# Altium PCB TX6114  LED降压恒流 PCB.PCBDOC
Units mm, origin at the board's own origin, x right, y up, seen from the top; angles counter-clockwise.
Board outline 33.78 x 21.25 mm, 2 copper layers (TopLayer, BottomLayer); 21 components, 9 nets, 48 pads, 36 vias.
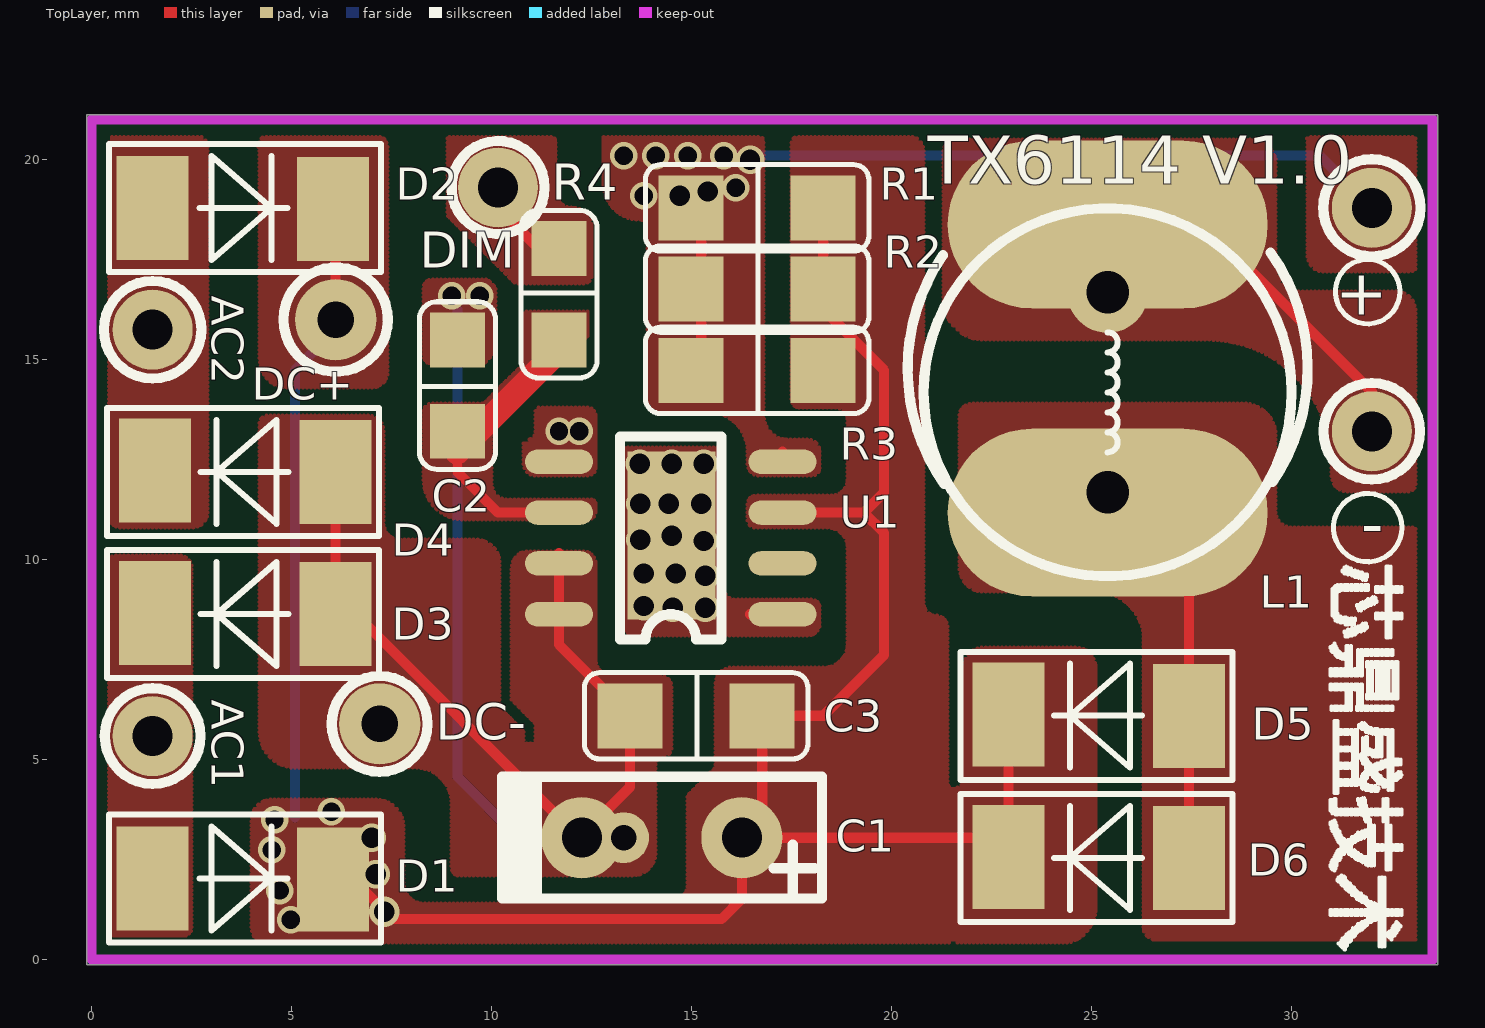
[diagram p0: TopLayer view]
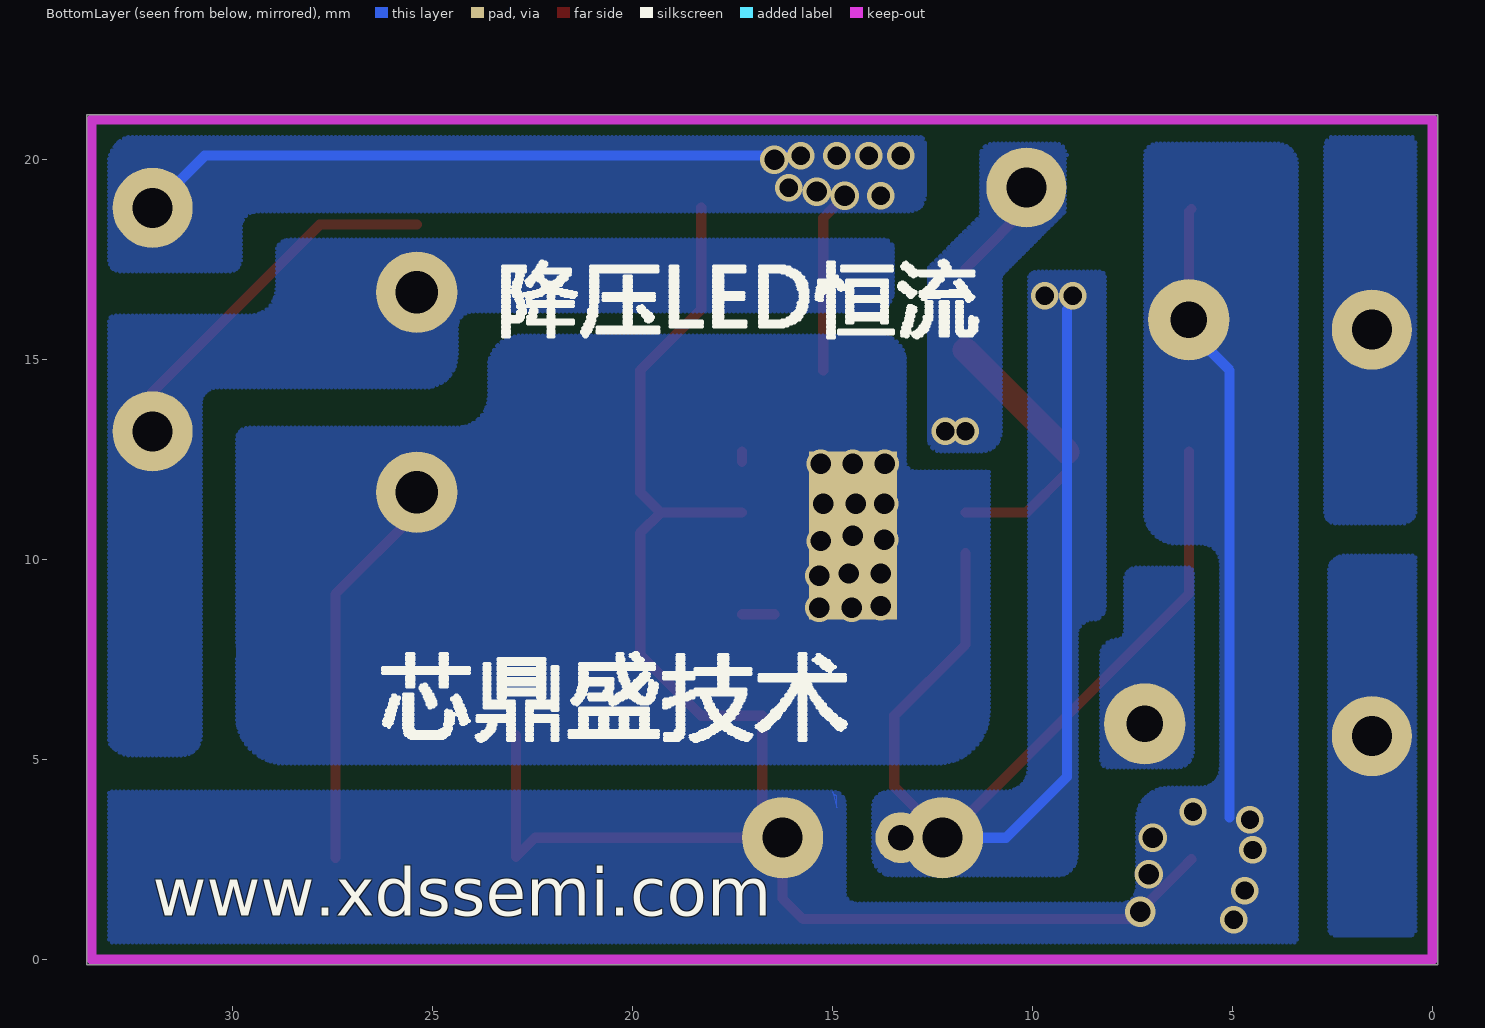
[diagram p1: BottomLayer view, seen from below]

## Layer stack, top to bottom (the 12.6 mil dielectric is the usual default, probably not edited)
TopLayer: signal copper 0.0356
Dielectric: dielectric 0.32, FR-4, Dk 4.8
BottomLayer: signal copper 0.0356

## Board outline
-0.127,-0.127 33.655,-0.127 33.655,21.127 -0.127,21.127

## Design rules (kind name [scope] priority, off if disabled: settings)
Clearance [All] p1: gap=0.254
ComponentClearance [All] p1 off: gap=0.254 collisioncheckmode=3 verticalgap=0.254 showdistances=FALSE
PolygonConnect [All] p1: connectstyle=Direct reliefconductorwidth=0.254 reliefentries=4 polygonreliefangle="90 Angle"
RoutingVias [All] p1: holewidth=0.711 width=1.27 viastyle="Through Hole" minholewidth=0.711 minwidth=1.27 maxholewidth=0.711 maxwidth=1.27
SilkscreenOverComponentPads [All] p1: minsilkscreentomaskgap=0.254
SolderMaskExpansion [All] p1: expansion=0.102
TestPointUsage [All] p1: valid=0 allowmultiple=FALSE
Testpoint [All] p1: side=15 testpointundercomponent=TRUE minsize=1.016 maxsize=2.54 preferedsize=1.524 minholesize=0.508 maxholesize=1.016 preferedholesize=0.813 testpointgrid=0.025 style=1023 order=0123456789
Width [All] p1: maxlimit=0.254 minlimit=0.254 preferedwidth=0.254
22 further rules are at their usual default settings.

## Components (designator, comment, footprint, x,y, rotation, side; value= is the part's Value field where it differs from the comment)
+ "" PAD 32.004,18.796 r0 top
- "" PAD 32.004,13.208 r0 top
AC1 "" PAD 1.524,5.588 r0 top
AC2 "" PAD 1.524,15.748 r0 top
C1 "" C8X 16.256,3.048 r90 top
C2 "" R0805 9.144,13.208 r0 top
C3 "" R1206 16.764,6.096 r270 top
D1 "" SMB 1.524,2.032 r0 top
D2 "" SMB 1.524,18.796 r0 top
D3 "" SMB 6.096,8.636 r180 top
D4 "" SMB 6.096,12.192 r180 top
D5 "" SMB 27.432,6.096 r180 top
D6 "" SMB 27.432,2.54 r180 top
DIM "" PAD 10.16,19.304 r0 top
L1 "" CD105 25.4,11.176 r90 top
R1 "" R1206 18.288,16.764 r270 top
R2 "" R1206 18.288,18.796 r270 top
R3 "" R1206 18.288,14.732 r270 top
R4 "" R0805 11.684,17.78 r180 top
U1 "TX6114" SOP8 17.272,8.636 r270 top
? "" L9*12 25.4,11.684 r90 top

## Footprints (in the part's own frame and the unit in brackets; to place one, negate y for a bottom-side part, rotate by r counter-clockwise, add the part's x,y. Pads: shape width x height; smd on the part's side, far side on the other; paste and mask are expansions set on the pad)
C8X [mil]
  round 80 hole 39.37: 1(0,0) 2(0,157.48)
  silkscreen extent -60,-79 60,236
CD105 [mm]
  oval 4.2x8 smd: 1(0,0) 2(7.2,0)
  silkscreen extent 0.72,-5 6.51,5
L9*12 [mil]
  round 80 hole 42: 1(0,0) 2(196.85,0)
  silkscreen extent -83,-181 279,181
PAD [mm]
  round 2 hole 1: 1(0,0)
R0805 [mil]
  rect 54x54 smd: 1(0,0) 2(0,90)
  silkscreen extent -38,-38 38,128
R1206 [mil]
  rect 64x64 smd: 1(0,0) 2(0,-130)
  silkscreen extent -43,-175 43,45
SMB [mm]
  rect 1.8x2.6 smd: 1(0,0) 2(4.511,-0.031)
  silkscreen extent -1.09,-1.6 5.71,1.6
SOP8 [mil]
  oval 24x66.93 smd: 1(0,0) 2(-50,0) 3(-100,0) 4(-150,0) 5(-150,-220) 6(-100,-220) 7(-50,-220) 8(0,-220)
  round 27.56 on Top Overlay: ""(-22.13,-84.65)
  silkscreen extent -175,-160 25,-60

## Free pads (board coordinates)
  round 2.032 hole 0.914: 1(7.2,5.893) 2(6.1,16)
  round 1.27 hole 0.635: 1(13.3,3.048)
  rect 2.2x4.2 all layers, no hole: 3(14.5,10.6)

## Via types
v1: diameter 0.711, hole 0.508, TopLayer to BottomLayer, 20 vias
v2: diameter 0.686, hole 0.457, TopLayer to BottomLayer, 15 vias
v3: diameter 0.762, hole 0.508, TopLayer to BottomLayer, 1 vias

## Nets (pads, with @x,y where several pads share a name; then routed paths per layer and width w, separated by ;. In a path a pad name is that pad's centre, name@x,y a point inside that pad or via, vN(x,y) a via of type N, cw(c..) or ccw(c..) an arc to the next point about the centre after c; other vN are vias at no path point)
NetAC1_1: AC1.1 D1.1 D3.2
NetAC2_1: AC2.1 D2.1 D4.2
NetC2_1: C2.1 R4.2 U1.6 | length 7.1
  TopLayer w0.254: C2.1@9.144,12.7 9.144,12.192 10.16,11.176 U1.6
  TopLayer w0.635: C2.1@9.144,12.7 9.398,12.954 R4.2@11.684,15.24
NetD6_1: ?.1 D5.1 D6.1 L1.1 pad.3 U1.1 | length 10.3
  TopLayer w0.254: U1.1@16.464,8.636 U1.1 ; L1.1 27.432,9.144 D5.1 D6.1
  other v1: 14.529,8.8 15.342,8.8 13.8,8.839 15.342,9.6 13.8,9.652 14.6,9.652 15.3,10.465 13.716,10.5 14.5,10.6 13.716,11.4 14.427,11.4 15.24,11.4 13.7,12.395 14.5,12.395 15.3,12.395
NetL1_2: -.1 ?.2 L1.2 | length 9.3
  TopLayer w0.254: L1.2 27.824,18.376 32.004,14.196 -.1
NetR2_2: +.1 R1.2 R2.2 R3.2 U1.4 | length 21.2
  TopLayer w0.254: R2.2 15.24,18.542 15.24,16.764 R3.2@15.24,14.732 ; U1.4 U1.4@17.272,12.7
  BottomLayer w0.254: v2(15.8,20.1) 16.459,20.1 30.7,20.1 +.1
  other v1: 14.7,19.101 15.4,19.202 16.459,20
  other v2: 13.8,19.1 16.1,19.3 13.3,20.1 14.1,20.1 14.9,20.1
NetR4_1: DIM.1 R4.1 U1.5 | length 2.2
  TopLayer w0.254: DIM.1@10.16,18.796 11.43,17.526 R4.1@11.684,17.272
  other v2: 11.684,13.208 12.192,13.208
VDC+: C1.1 C3.1 D1.2 D2.2 D5.2 D6.2 pad.2 R1.1 R2.1 R3.1 U1.3 | length 59.3
  TopLayer w0.254: D1.2@6.035,2.509 6.289,2.255 7.329,1.214 7.528,1.016 15.748,1.016 16.256,1.524 C1.1 ; D2.2 6.096,18.704 6.096,16 pad.2@6.096,15.748 ; U1.3 19.304,11.176 ; R2.1 R1.1 18.288,16.256 19.05,15.494 19.812,14.732 19.812,11.684 19.304,11.176 ; D5.2@22.921,5.619 D6.2 22.444,3.048 C1.1 ; C1.1 16.764,3.556 C3.1 18.288,6.096 19.812,7.62 19.812,10.668 19.304,11.176
  BottomLayer w0.254: 5.08,3.556 5.08,14.732 pad.2@6.096,15.748
  other v1: 7.1,2.134 7,3.048
  other v2: 4.978,1 4.7,1.727 4.5,2.743 4.572,3.5 5.994,3.7
  other v3: 7.315,1.2
VDC-: C1.2 C2.2 C3.2 D3.1 D4.1 pad.1 U1.7 U1.8 | length 36
  TopLayer w0.254: D4.1@6.096,12.7 D4.1 6.096,9.144 6.35,8.89 12.192,3.048 12.224,3.08 13.462,4.318 C3.2 11.684,7.874 U1.8 U1.7 U1.7@11.684,10.16
  BottomLayer w0.254: 9.144,16.256 9.144,4.572 10.668,3.048 C1.2
  other v2: 9,16.6 9.7,16.6
pads on no net: U1. U1.2

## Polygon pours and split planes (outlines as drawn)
VDC- on TopLayer "TopLayer-VDC-" (hatched 90Degree grid 0.102 track 0.102, remove dead copper, pour order 1000): 8.5,17 9.9,17 10.1,16.8 10.1,15.2 9.8,14.9 8.5,14.9 cw(c8.5,15.1) 8.3,15.1 8.3,16.8 cw(c8.5,16.8) 8.5,17
NetC2_1 on TopLayer "TopLayer-NetC2_1" (hatched 90Degree grid 0.102 track 0.102, remove dead copper, pour order 1001): 10.8,16.2 10.8,14.9 9.8,13.9 8.5,13.9 ccw(c8.5,13.7) 8.3,13.7 8.3,12 ccw(c9.3,12) 9.3,11 12.4,11 ccw(c12.4,11.2) 12.6,11.2 12.6,11.4 ccw(c12.5,11.4) 12.5,11.5 10.4,11.5 cw(c10.4,11.9) 10,11.9 10,13.2 12.4,15.6 12.4,16.2
VDC- on TopLayer "TopLayer-VDC- 1" (hatched 90Degree grid 0.102 track 0.102, remove dead copper, pour order 1002): 4.2,13.4 4.2,5.7 ccw(c5.1,5.7) 5.1,4.8 8.1,4.8 cw(c8.1,3.9) 9,3.9 9,2.3 ccw(c9.2,2.3) 9.2,2.1 13.5,2.1 ccw(c13.5,2.7) 14.1,2.7 14.1,4.9 cw(c14.3,4.9) 14.3,5.1 ccw(c14.3,5.3) 14.5,5.3 14.5,6.8 ccw(c14.2,6.8) 14.2,7.1 13,7.1 cw(c13,7.5) 12.6,7.5 12.6,9.9 ccw(c12.3,9.9) 12.3,10.2 10.9,10.2 ccw(c10.9,9.8) 10.5,9.8 10.5,6.5 11.1,5.9 11.1,5.4 10.8,5.4 10.8,5.7 10.2,6.3 10.2,9.9 ccw(c9.6,9.9) 9.6,10.5 7.7,10.5 cw(c7.7,10.9) 7.3,10.9 7.3,13.2 ccw(c6.9,13.2) 6.9,13.6 4.4,13.6 ccw(c4.4,13.4)
VDC+ on TopLayer "TopLayer-VDC+" (hatched 90Degree grid 0.102 track 0.102, remove dead copper, pour order 1003): 4.2,20.3 4.2,15 ccw(c4.9,15) 4.9,14.3 7,14.3 ccw(c7,14.7) 7.4,14.7 7.4,20.3 ccw(c7.1,20.3) 7.1,20.6 4.4,20.6 ccw(c4.4,20.4) 4.2,20.4
NetD6_1 on TopLayer "TopLayer-NetD6_1" (hatched 90Degree grid 0.102 track 0.102, remove dead copper, pour order 1004): 13.3,12.8 13.3,8.4 ccw(c13.6,8.4) 13.6,8.1 17.9,8.1 ccw(c17.9,8.4) 18.2,8.4 18.2,8.8 ccw(c18,8.8) 18,9 16.1,9 cw(c16.1,9.3) 15.8,9.3 15.8,12.8
NetR4_1 on TopLayer "TopLayer-NetR4_1" (hatched 90Degree grid 0.102 track 0.102, remove dead copper, pour order 1005): 8.9,20.4 8.9,18.6 10.6,16.9 12.3,16.9 ccw(c12.3,17.1) 12.5,17.1 12.5,18.3 ccw(c12,18.3) 12,18.8 cw(c12,19.2) 11.6,19.2 11.6,20.4 ccw(c11.3,20.4) 11.3,20.7 9,20.7 ccw(c9,20.6) 8.9,20.6
NetR2_2 on TopLayer "TopLayer-NetR2_2" (hatched 90Degree grid 0.102 track 0.102, remove dead copper, pour order 1006): 30.4,20.5 30.4,17.6 ccw(c30.8,17.6) 30.8,17.2 32.9,17.2 ccw(c32.9,17.6) 33.3,17.6 33.3,20.5 ccw(c33,20.5) 33,20.8 30.5,20.8 ccw(c30.5,20.7) 30.4,20.7
NetR4_1 on TopLayer "TopLayer-NetR4_1 1" (hatched 90Degree grid 0.102 track 0.102, remove dead copper, pour order 1007): 10.8,13.5 10.8,12.4 ccw(c11.1,12.4) 11.1,12.1 12.4,12.1 ccw(c12.4,12.3) 12.6,12.3 12.6,13.6 ccw(c12.4,13.6) 12.4,13.8 11.2,13.8 ccw(c11.2,13.7) 11.1,13.7 11.1,13.2 cw(c10.9,13.2) 10.9,13 10.8,13
NetD6_1 on TopLayer "TopLayer-NetD6_1 1" (hatched 90Degree grid 0.102 track 0.102, remove dead copper, pour order 1008): 21.7,13.2 21.7,9.8 ccw(c22.3,9.8) 22.3,9.2 25.1,9.2 cw(c25.1,8) 26.3,8 26.3,0.8 ccw(c26.6,0.8) 26.6,0.5 33.8,0.5 33.8,10.3 ccw(c33.3,10.3) 33.3,10.8 30,10.8 cw(c30,11.2) 29.6,11.2 29.6,13.1 ccw(c28.8,13.1) 28.8,13.9 22,13.9 ccw(c22,13.6) 21.7,13.6
VDC+ on TopLayer "TopLayer-VDC+ 1" (hatched 90Degree grid 0.102 track 0.102, remove dead copper, pour order 1009): 17.5,20.4 17.5,14 ccw(c17.7,14) 17.7,13.8 18.6,13.8 cw(c18.6,13.5) 18.9,13.5 18.9,12 cw(c18.5,12) 18.5,11.6 16.6,11.6 ccw(c16.6,11.4) 16.4,11.4 16.4,11 ccw(c16.6,11) 16.6,10.8 18.4,10.8 cw(c18.4,10.3) 18.9,10.3 18.9,7.9 cw(c18.3,7.9) 18.3,7.3 16,7.3 ccw(c16,6.9) 15.6,6.9 15.6,4.8 14.9,4.1 14.9,1.9 cw(c14.4,1.9) 14.4,1.4 8.3,1.4 cw(c8.3,1.9) 7.8,1.9 7.8,3.3 ccw(c7.1,3.3) 7.1,4 4.5,4 ccw(c4.5,3.5) 4,3.5 4,0.8 ccw(c4.4,0.8) 4.4,0.4 24.2,0.4 ccw(c24.2,1.3) 25.1,1.3 25.1,7.3 ccw(c24.6,7.3) 24.6,7.8 22.3,7.8 ccw(c22.3,7.3) 21.8,7.3 21.8,4.5 cw(c21.6,4.5) 21.6,4.3 21.5,4.3 cw(c21.5,4.4) 21.4,4.4 21.4,8.3 ccw(c21.1,8.3) 21.1,8.6 cw(c21.1,8.9) 20.8,8.9 20.8,20.2 ccw(c20.4,20.2) 20.4,20.6 17.7,20.6 ccw(c17.7,20.4)
NetL1_2 on TopLayer "TopLayer-NetL1_2" (hatched 90Degree grid 0.102 track 0.102, remove dead copper, pour order 1010): 21.3,20 21.3,16.5 ccw(c22.3,16.5) 22.3,15.5 27.9,15.5 cw(c27.9,12.4) 31,12.4 31,12.1 ccw(c31.4,12.1) 31.4,11.7 32.9,11.7 ccw(c32.9,11.9) 33.1,11.9 33.1,16.2 ccw(c32.6,16.2) 32.6,16.7 30.2,16.7 cw(c30.2,17.3) 29.6,17.3 29.6,19.9 ccw(c29,19.9) 29,20.5 21.6,20.5 ccw(c21.6,20.2) 21.3,20.2
NetR2_2 on TopLayer "TopLayer-NetR2_2 1" (hatched 90Degree grid 0.102 track 0.102, remove dead copper, pour order 1011): 12.8,20.6 12.8,19.4 ccw(c13.7,19.4) 13.7,18.5 cw(c13.7,18.3) 13.9,18.3 13.9,14.1 ccw(c14.3,14.1) 14.3,13.7 15.4,13.7 cw(c15.4,12.7) 16.4,12.7 16.4,12.4 ccw(c16.7,12.4) 16.7,12.1 18,12.1 ccw(c18,12.3) 18.2,12.3 18.2,12.7 ccw(c17.9,12.7) 17.9,13 17.4,13 cw(c17.4,13.6) 16.8,13.6 16.8,20.4 ccw(c16.5,20.4) 16.5,20.7 12.9,20.7
NetAC1_1 on TopLayer "TopLayer-NetAC1_1" (hatched 90Degree grid 0.102 track 0.102, remove dead copper, pour order 1012): 0.4,9.9 0.4,0.8 ccw(c0.6,0.8) 0.6,0.6 2.3,0.6 ccw(c2.3,0.8) 2.5,0.8 2.5,9.8 ccw(c2.2,9.8) 2.2,10.1 0.6,10.1 ccw(c0.6,9.9)
NetAC2_1 on TopLayer "TopLayer-NetAC2_1" (hatched 90Degree grid 0.102 track 0.102, remove dead copper, pour order 1013): 0.435,20.396 0.435,11.1 ccw(c0.735,11.1) 0.735,10.8 2.5,10.8 ccw(c2.5,11.2) 2.9,11.2 2.9,20.3 ccw(c2.6,20.3) 2.6,20.6 0.6,20.6 ccw(c0.6,20.4) 0.4,20.4
VDC- on BottomLayer "BottomLayer-VDC-" (hatched 90Degree grid 0.102 track 0.102, remove dead copper, pour order 1014): 6,9.5 6,5.2 ccw(c6.4,5.2) 6.4,4.8 8.1,4.8 ccw(c8.1,5) 8.3,5 8.3,7.6 ccw(c7.9,7.6) 7.9,8 cw(c7.9,8.2) 7.7,8.2 7.7,9.5 ccw(c7.4,9.5) 7.4,9.8 6.1,9.8 ccw(c6.1,9.7) 6,9.7
NetAC1_1 on BottomLayer "BottomLayer-NetAC1_1" (hatched 90Degree grid 0.102 track 0.102, remove dead copper, pour order 1015): 0.4,9.7 0.4,0.8 ccw(c0.6,0.8) 0.6,0.6 2.4,0.6 ccw(c2.4,0.8) 2.6,0.8 2.6,9.7 ccw(c2.2,9.7) 2.2,10.1 0.5,10.1 ccw(c0.5,10) 0.4,10
NetAC2_1 on BottomLayer "BottomLayer-NetAC2_1" (hatched 90Degree grid 0.102 track 0.102, remove dead copper, pour order 1016): 0.4,20.3 0.4,11.3 ccw(c0.8,11.3) 0.8,10.9 2.4,10.9 ccw(c2.4,11.2) 2.7,11.2 2.7,20.3 ccw(c2.4,20.3) 2.4,20.6 0.6,20.6 ccw(c0.6,20.4) 0.4,20.4
NetL1_2 on BottomLayer "BottomLayer-NetL1_2" (hatched 90Degree grid 0.102 track 0.102, remove dead copper, pour order 1017): 14.2,18 28.6,18 cw(c28.6,17.7) 28.9,17.7 28.9,16.8 ccw(c29.6,16.8) 29.6,16.1 32.9,16.1 cw(c32.9,15.8) 33.2,15.8 33.2,5.8 cw(c32.5,5.8) 32.5,5.1 31.3,5.1 cw(c31.3,5.6) 30.8,5.6 30.8,13.9 ccw(c30.4,13.9) 30.4,14.3 25.2,14.3 cw(c25.2,15.1) 24.4,15.1 24.4,15.8 ccw(c24,15.8) 24,16.2 14,16.2 cw(c14,16.7) 13.5,16.7 13.5,17.8 cw(c13.7,17.8) 13.7,18
VDC+ on BottomLayer "BottomLayer-VDC+" (hatched 90Degree grid 0.102 track 0.102, remove dead copper, pour order 1018): 17.78,4.2 34.1,4.2 34.1,-2.1 16,-2.1 16,4.2
VDC- on BottomLayer "BottomLayer-VDC- 1" (hatched 90Degree grid 0.102 track 0.102, remove dead copper, pour order 1019): 8.2,16.9 8.2,8.8 ccw(c8.5,8.8) 8.5,8.5 cw(c8.5,8.1) 8.9,8.1 8.9,2.6 ccw(c9.4,2.6) 9.4,2.1 13.5,2.1 ccw(c13.5,2.6) 14,2.6 14,3.8 ccw(c13.6,3.8) 13.6,4.2 10.7,4.2 cw(c10.7,4.8) 10.1,4.8 10.1,17 ccw(c9.9,17) 9.9,17.2 8.3,17.2 ccw(c8.3,17.1) 8.2,17.1
VDC+ on BottomLayer "BottomLayer-VDC+ 1" (hatched 90Degree grid 0.102 track 0.102, remove dead copper, pour order 1020): 14.7,2 14.7,3.9 cw(c15,3.9) 15,4.2 17.9,4.2 cw(c17.9,3.9) 18.2,3.9 18.2,-0.5 3.8,-0.5 cw(c3.8,-0.1) 3.4,-0.1 3.4,19.9 cw(c3.9,19.9) 3.9,20.4 6.9,20.4 cw(c6.9,20.1) 7.2,20.1 7.2,11.2 cw(c6.4,11.2) 6.4,10.4 5.8,10.4 ccw(c5.8,9.9) 5.3,9.9 5.3,4.8 ccw(c5.8,4.8) 5.8,4.3 6.6,4.3 cw(c6.6,3.5) 7.4,3.5 7.4,1.8 ccw(c7.8,1.8) 7.8,1.4 14.4,1.4 ccw(c14.4,1.7) 14.7,1.7
VDC+ on BottomLayer "BottomLayer-VDC+ 2" (hatched 90Degree grid 0.102 track 0.102, remove dead copper, pour order 1021): 14.9,3.8 14.9,4.1 ccw(c14.9,4.2) 15,4.2
NetD6_1 on BottomLayer "BottomLayer-NetD6_1" (hatched 90Degree grid 0.102 track 0.102, remove dead copper, pour order 1022): 10.9,12.2 12.9,12.2 ccw(c12.9,12.5) 13.2,12.5 13.2,15 cw(c13.8,15) 13.8,15.6 22.8,15.6 cw(c22.8,14.8) 23.6,14.8 23.6,14.1 ccw(c24.4,14.1) 24.4,13.3 29.6,13.3 cw(c29.6,13) 29.9,13 29.9,8 cw(c29.1,8) 29.1,7.2 ccw(c29.1,8) 29.9,8 29.9,6.1 cw(c28.7,6.1) 28.7,4.9 12.4,4.9 cw(c12.4,6.2) 11.1,6.2 11.1,12.2
NetR4_1 on BottomLayer "BottomLayer-NetR4_1" (hatched 90Degree grid 0.102 track 0.102, remove dead copper, pour order 1023): 9.2,20.1 9.2,18.7 10.8,17.1 10.8,13.2 ccw(c11.3,13.2) 11.3,12.7 12.3,12.7 ccw(c12.3,13) 12.6,13 12.6,17.3 11.3,18.6 11.3,20.1 ccw(c11,20.1) 11,20.4 9.4,20.4 ccw(c9.4,20.2) 9.2,20.2
NetR2_2 on BottomLayer "BottomLayer-NetR2_2" (hatched 90Degree grid 0.102 track 0.102, remove dead copper, pour order 1024): 12.9,20.6 32.4,20.6 cw(c32.4,19.9) 33.1,19.9 33.1,17.5 cw(c32.8,17.5) 32.8,17.2 30.1,17.2 cw(c30.1,17.5) 29.8,17.5 29.8,18.3 ccw(c29.4,18.3) 29.4,18.7 13.1,18.7 cw(c13.1,19.1) 12.7,19.1 12.7,20.4 cw(c12.9,20.4)
no net on BottomLayer "BottomLayer-No Net" (hatched 90Degree grid 0.508 track 0.203, remove dead copper, pour order 1025): 8.636,3.556
NetD6_1 on BottomSolder (hatched 90Degree grid 0.102 track 0.102, remove dead copper): 13.5,12.7 13.5,13.3 cw(c13.8,13.3) 13.8,13.6 29.1,13.6 cw(c29.1,13.2) 29.5,13.2 29.5,8.5 cw(c29.1,8.5) 29.1,8.1 13.7,8.1 cw(c13.7,8.3) 13.5,8.3

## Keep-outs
KeepOutLayer:
  lines w0.254: 0,0 0,21 33.528,21 33.528,0 0,0

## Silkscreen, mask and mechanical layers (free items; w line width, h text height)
TopOverlay:
  drawing of 713 lines, arcs and shapes, not listed
  text "TX6114 V1.0" at 20.9,19.4 h1.2
  text "DC+" at 4,14 h0.8
  text "DC-" at 8.6,5.5 h0.9
BottomOverlay:
  drawing of 1667 lines, arcs and shapes, not listed
  text "www.xdssemi.com" at 32,1.1 h1.2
